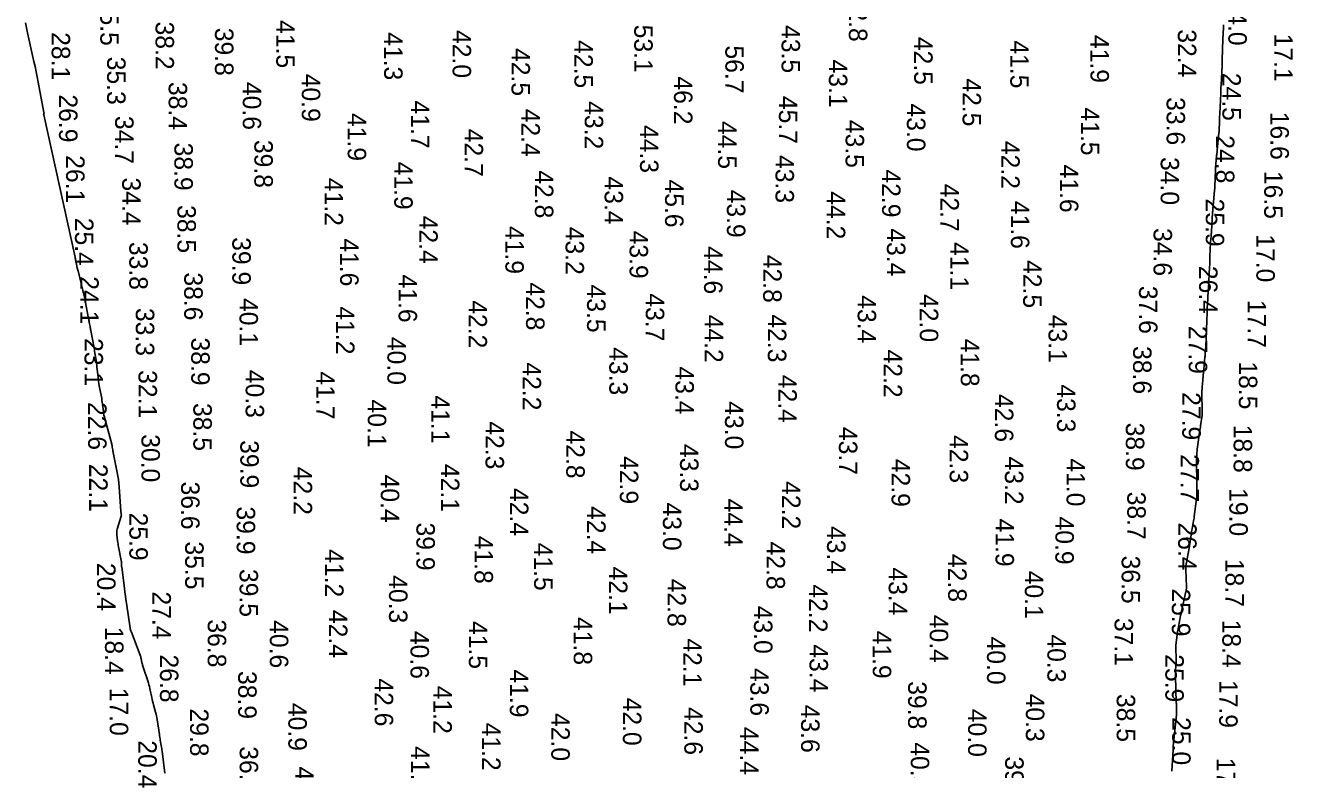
# Model space of a CAD drawing. Extents: x 1178573 to 1187098, y 693282 to 751751.
# Drawn here: x 1180803 to 1181661, y 700285 to 700789 of the extents above; entities that cross this region are included whole.
import ezdxf

# ---------------------------------------------------------------- set-up
doc = ezdxf.new("R2010")
doc.units = 0
doc.layers.add('V-HYDS-MAJR', color=7, linetype='Continuous')
doc.layers.add('V-HYDS-SOUN', color=7, linetype='Continuous')

msp = doc.modelspace()

# ---------------------------------------------------------------- linework, layer by layer
at = {"layer": 'V-HYDS-MAJR'}
for points in [[(1180897.25, 700282.8), (1180895.47, 700297.61), (1180895.35, 700298.55), (1180895.22, 700299.49), (1180895.07, 700300.43), (1180894.92, 700301.37), (1180894.28, 700305.11), (1180894.12, 700306.05), (1180893.97, 700306.98), (1180893.83, 700307.92), (1180893.69, 700308.86), (1180892.21, 700319.05), (1180892, 700320.31), (1180891.75, 700321.56), (1180891.46, 700322.8), (1180891.12, 700324.03), (1180889.69, 700328.93), (1180889.35, 700330.16), (1180889.03, 700331.4), (1180888.74, 700332.64), (1180888.47, 700333.89), (1180887.47, 700338.91), (1180887.2, 700340.16), (1180886.89, 700341.4), (1180886.55, 700342.63), (1180886.18, 700343.85), (1180882.5, 700355.26), (1180882.31, 700355.86), (1180882.14, 700356.47), (1180881.99, 700357.08), (1180881.85, 700357.7), (1180881.33, 700360.18), (1180881.19, 700360.8), (1180881.03, 700361.41), (1180880.84, 700362.01), (1180880.62, 700362.61), (1180874.68, 700378.19), (1180874.59, 700378.42), (1180874.51, 700378.65), (1180874.43, 700378.89), (1180874.36, 700379.13), (1180873.96, 700380.49), (1180873.94, 700380.56), (1180873.91, 700380.64), (1180873.87, 700380.79), (1180873.86, 700380.82), (1180873.85, 700380.86), (1180873.84, 700380.9), (1180873.84, 700380.94), (1180871.33, 700397.78), (1180870.96, 700400.3), (1180870.61, 700402.82), (1180870.27, 700405.35), (1180869.95, 700407.88), (1180868.14, 700422.31), (1180868.09, 700422.69), (1180868.06, 700423.06), (1180868.03, 700423.44), (1180868.01, 700423.82), (1180867.95, 700425.32), (1180867.93, 700425.7), (1180867.89, 700426.07), (1180867.84, 700426.45), (1180867.77, 700426.82), (1180866.03, 700435.89), (1180865.84, 700436.9), (1180865.67, 700437.91), (1180865.52, 700438.92), (1180865.38, 700439.93), (1180864.85, 700443.99), (1180864.77, 700445), (1180864.8, 700446), (1180864.93, 700446.99), (1180865.17, 700447.98), (1180867.82, 700456.82), (1180867.88, 700457.09), (1180867.91, 700457.35), (1180867.91, 700457.61), (1180867.88, 700457.88), (1180867.69, 700458.95), (1180867.65, 700459.22), (1180867.61, 700459.49), (1180867.58, 700459.76), (1180867.56, 700460.03), (1180866.37, 700476.62), (1180866.16, 700479.06), (1180865.87, 700481.48), (1180865.5, 700483.89), (1180865.06, 700486.29), (1180862.35, 700499.73), (1180862.26, 700500.2), (1180862.18, 700500.67), (1180862.1, 700501.14), (1180862.04, 700501.62), (1180861.78, 700503.52), (1180861.7, 700504), (1180861.62, 700504.47), (1180861.51, 700504.93), (1180861.4, 700505.4), (1180856.68, 700522.73), (1180856.38, 700523.95), (1180856.11, 700525.17), (1180855.89, 700526.4), (1180855.72, 700527.64), (1180855.11, 700532.61), (1180854.95, 700533.86), (1180854.77, 700535.09), (1180854.57, 700536.33), (1180854.35, 700537.56), (1180852.96, 700544.98), (1180852.7, 700546.47), (1180852.47, 700547.97), (1180852.26, 700549.47), (1180852.09, 700550.98), (1180851.39, 700557.65), (1180851.25, 700558.84), (1180851.1, 700560.02), (1180850.94, 700561.21), (1180850.76, 700562.39), (1180850, 700567.13), (1180849.81, 700568.31), (1180849.61, 700569.49), (1180849.4, 700570.67), (1180849.19, 700571.85), (1180847.22, 700582.52), (1180847.09, 700583.19), (1180846.97, 700583.87), (1180846.84, 700584.55), (1180846.72, 700585.22), (1180846.21, 700587.93), (1180846.09, 700588.6), (1180845.96, 700589.28), (1180845.83, 700589.96), (1180845.69, 700590.63), (1180842.64, 700606), (1180842.59, 700606.29), (1180842.53, 700606.57), (1180842.46, 700606.86), (1180842.4, 700607.14), (1180842.13, 700608.28), (1180842.06, 700608.56), (1180841.99, 700608.85), (1180841.92, 700609.13), (1180841.85, 700609.41), (1180838.64, 700622.76), (1180838.63, 700622.79), (1180838.62, 700622.8), (1180838.61, 700622.79), (1180838.61, 700622.76), (1180838.57, 700622.61), (1180838.57, 700622.58), (1180838.56, 700622.57), (1180838.55, 700622.58), (1180838.54, 700622.61), (1180837.99, 700624.75), (1180837.9, 700625.12), (1180837.81, 700625.49), (1180837.74, 700625.86), (1180837.66, 700626.23), (1180837.07, 700629.49), (1180836.95, 700630.16), (1180836.82, 700630.82), (1180836.68, 700631.49), (1180836.54, 700632.15), (1180815.3, 700728.32), (1180815.27, 700728.45), (1180815.27, 700728.58), (1180815.29, 700728.71), (1180815.32, 700728.84), (1180815.47, 700729.35), (1180815.5, 700729.48), (1180815.52, 700729.6), (1180815.52, 700729.73), (1180815.5, 700729.87), (1180811.56, 700750.57), (1180810.88, 700754.07), (1180810.18, 700757.55), (1180809.44, 700761.03), (1180808.69, 700764.51), (1180804.36, 700783.94), (1180803.61, 700787.36), (1180802.87, 700790.78)], [(1181614.43, 700789.25), (1181614.41, 700788.67), (1181614.34, 700786.38), (1181614.32, 700785.81), (1181614.3, 700785.24), (1181614.28, 700784.66), (1181614.25, 700784.09), (1181613.77, 700773.52), (1181613.72, 700772.27), (1181613.67, 700771.03), (1181613.63, 700769.78), (1181613.6, 700768.53), (1181613.46, 700761.77), (1181613.45, 700761.41), (1181613.44, 700761.05), (1181613.43, 700760.69), (1181613.42, 700760.33), (1181613.38, 700758.89), (1181613.36, 700758.53), (1181613.35, 700758.18), (1181613.33, 700757.82), (1181613.31, 700757.46), (1181612.77, 700748.33), (1181612.71, 700747.18), (1181612.66, 700746.04), (1181612.61, 700744.9), (1181612.57, 700743.75), (1181612.37, 700737.32), (1181612.36, 700737.1), (1181612.35, 700736.89), (1181612.34, 700736.68), (1181612.32, 700736.47), (1181612.26, 700735.62), (1181612.25, 700735.41), (1181612.23, 700735.2), (1181612.22, 700734.99), (1181612.21, 700734.78), (1181611.87, 700728.51), (1181611.81, 700727.39), (1181611.76, 700726.28), (1181611.72, 700725.16), (1181611.67, 700724.05), (1181611.45, 700717.52), (1181611.44, 700717.26), (1181611.42, 700716.99), (1181611.39, 700716.73), (1181611.36, 700716.46), (1181611.19, 700715.41), (1181611.16, 700715.15), (1181611.12, 700714.89), (1181611.09, 700714.62), (1181611.06, 700714.36), (1181609.84, 700701.59), (1181609.77, 700700.85), (1181609.7, 700700.11), (1181609.63, 700699.37), (1181609.56, 700698.63), (1181609.17, 700694.42), (1181609.16, 700694.31), (1181609.15, 700694.19), (1181609.14, 700694.07), (1181609.14, 700693.96), (1181609.1, 700693.49), (1181609.09, 700693.37), (1181609.09, 700693.25), (1181609.08, 700693.13), (1181609.07, 700693.02), (1181608.72, 700683.56), (1181608.65, 700681.95), (1181608.56, 700680.33), (1181608.44, 700678.72), (1181608.31, 700677.11), (1181607.39, 700667.07), (1181607.35, 700666.64), (1181607.32, 700666.22), (1181607.28, 700665.8), (1181607.25, 700665.37), (1181607.12, 700663.68), (1181607.09, 700663.25), (1181607.06, 700662.83), (1181607.03, 700662.41), (1181607, 700661.98), (1181606.25, 700649.5), (1181606.19, 700648.62), (1181606.13, 700647.75), (1181606.06, 700646.87), (1181605.99, 700646), (1181605.7, 700642.5), (1181605.63, 700641.63), (1181605.57, 700640.75), (1181605.53, 700639.87), (1181605.49, 700639), (1181605.23, 700630.84), (1181605.18, 700629.51), (1181605.13, 700628.19), (1181605.07, 700626.86), (1181605, 700625.53), (1181604.73, 700620.22), (1181604.66, 700618.9), (1181604.59, 700617.57), (1181604.51, 700616.24), (1181604.43, 700614.92), (1181604.05, 700608.58), (1181603.98, 700607.48), (1181603.91, 700606.38), (1181603.84, 700605.29), (1181603.77, 700604.19), (1181603.47, 700599.81), (1181603.41, 700598.71), (1181603.35, 700597.61), (1181603.3, 700596.51), (1181603.27, 700595.42), (1181603.08, 700588.38), (1181603.04, 700586.84), (1181602.99, 700585.3), (1181602.93, 700583.77), (1181602.87, 700582.23), (1181602.43, 700571.71), (1181602.4, 700571.11), (1181602.37, 700570.5), (1181602.33, 700569.89), (1181602.28, 700569.28), (1181602.09, 700566.85), (1181602.03, 700566.24), (1181601.98, 700565.63), (1181601.92, 700565.02), (1181601.86, 700564.42), (1181600.76, 700553.46), (1181600.65, 700552.3), (1181600.54, 700551.14), (1181600.43, 700549.98), (1181600.34, 700548.82), (1181599.96, 700544.17), (1181599.88, 700543.01), (1181599.83, 700541.84), (1181599.81, 700540.68), (1181599.82, 700539.51), (1181600.06, 700528.19), (1181600.06, 700527.07), (1181600.01, 700525.96), (1181599.92, 700524.84), (1181599.78, 700523.73), (1181599.12, 700519.29), (1181598.95, 700518.18), (1181598.79, 700517.07), (1181598.63, 700515.96), (1181598.47, 700514.85), (1181596.65, 700502.15), (1181596.56, 700501.4), (1181596.48, 700500.65), (1181596.42, 700499.9), (1181596.38, 700499.15), (1181596.26, 700496.14), (1181596.24, 700495.39), (1181596.22, 700494.63), (1181596.22, 700493.88), (1181596.22, 700493.12), (1181596.44, 700478.96), (1181596.45, 700478.08), (1181596.46, 700477.2), (1181596.46, 700476.32), (1181596.45, 700475.44), (1181596.43, 700471.91), (1181596.41, 700471.03), (1181596.36, 700470.16), (1181596.29, 700469.28), (1181596.18, 700468.41), (1181594.62, 700456.44), (1181594.48, 700455.4), (1181594.32, 700454.38), (1181594.15, 700453.35), (1181593.97, 700452.33), (1181593.21, 700448.23), (1181593.02, 700447.21), (1181592.84, 700446.18), (1181592.67, 700445.16), (1181592.51, 700444.13), (1181591.14, 700435.11), (1181590.94, 700433.89), (1181590.73, 700432.68), (1181590.51, 700431.48), (1181590.26, 700430.27), (1181589.26, 700425.46), (1181589.05, 700424.25), (1181588.91, 700423.04), (1181588.85, 700421.82), (1181588.87, 700420.6), (1181589.36, 700408.99), (1181589.37, 700408.72), (1181589.36, 700408.44), (1181589.34, 700408.17), (1181589.31, 700407.9), (1181589.16, 700406.83), (1181589.11, 700406.56), (1181589.07, 700406.29), (1181589.02, 700406.02), (1181588.96, 700405.75), (1181585.96, 700392.28), (1181585.66, 700390.92), (1181585.38, 700389.54), (1181585.11, 700388.17), (1181584.85, 700386.79), (1181583.71, 700380.47), (1181583.54, 700379.5), (1181583.37, 700378.53), (1181583.22, 700377.55), (1181583.07, 700376.57), (1181582.5, 700372.66), (1181582.38, 700371.68), (1181582.29, 700370.7), (1181582.24, 700369.72), (1181582.23, 700368.73), (1181582.3, 700358.75), (1181582.3, 700357.89), (1181582.28, 700357.02), (1181582.25, 700356.16), (1181582.21, 700355.3), (1181582, 700351.84), (1181581.95, 700350.98), (1181581.93, 700350.11), (1181581.92, 700349.25), (1181581.94, 700348.39), (1181582.47, 700330.69), (1181582.49, 700329.99), (1181582.51, 700329.28), (1181582.53, 700328.57), (1181582.55, 700327.87), (1181582.61, 700325.04), (1181582.62, 700324.34), (1181582.6, 700323.63), (1181582.56, 700322.93), (1181582.5, 700322.23), (1181580.73, 700305.42), (1181580.67, 700304.87), (1181580.62, 700304.31), (1181580.58, 700303.76), (1181580.54, 700303.2), (1181580.39, 700300.98), (1181580.35, 700300.43), (1181580.31, 700299.87), (1181580.28, 700299.32), (1181580.25, 700298.76), (1181579.35, 700284.18)]]:
    msp.add_lwpolyline(points, dxfattribs=at)

# ---------------------------------------------------------------- texts
at = {"layer": 'V-HYDS-SOUN'}
for s, p in [('35.5 ', (1180853.65, 700807.64)), ('42.8 ', (1181360.67, 700810.42)), ('24.0 ', (1181617.71, 700807.8)), ('38.2 ', (1180891.06, 700791.55)), ('39.8 ', (1180931.34, 700787.35)), ('41.5 ', (1180972.84, 700792.52)), ('53.1 ', (1181215.3, 700789.45)), ('43.5 ', (1181315.1, 700789.14)), ('28.1 ', (1180820.71, 700784.39)), ('41.3 ', (1181045.89, 700784.34)), ('42.0 ', (1181092.28, 700785.82)), ('42.5 ', (1181174.78, 700778.97)), ('42.5 ', (1181404.89, 700781.2)), ('41.5 ', (1181470.02, 700778.81)), ('41.9 ', (1181524.32, 700782.5)), ('32.4 ', (1181583.49, 700786.32)), ('17.1 ', (1181648.76, 700783.41)), ('42.5 ', (1181132.16, 700773.62)), ('56.7 ', (1181277, 700775.38)), ('35.3 ', (1180858.26, 700767.74)), ('43.1 ', (1181347.12, 700765.86)), ('40.9 ', (1180990.13, 700756.22)), ('46.2 ', (1181242.21, 700754.41)), ('42.5 ', (1181437.7, 700753.08)), ('24.5 ', (1181613.69, 700756.86)), ('38.4 ', (1180899.96, 700750.69)), ('40.6 ', (1180950.13, 700750.68)), ('26.9 ', (1180825.69, 700742.24)), ('41.7 ', (1181064.07, 700738.11)), ('43.2 ', (1181181.78, 700737.65)), ('45.7 ', (1181313.28, 700741.23)), ('43.0 ', (1181399.99, 700736.09)), ('33.6 ', (1181575.88, 700740.37)), ('34.7 ', (1180863.68, 700727.68)), ('41.9 ', (1181021.23, 700729.65)), ('42.4 ', (1181138.91, 700732.58)), ('41.5 ', (1181517.85, 700733.37)), ('16.6 ', (1181646.22, 700730.47)), ('42.7 ', (1181100.42, 700718.98)), ('44.3 ', (1181219.22, 700721.54)), ('44.5 ', (1181272.08, 700724.24)), ('43.5 ', (1181358.47, 700725.03)), ('38.9 ', (1180903.84, 700709.6)), ('39.8 ', (1180958.01, 700711.44)), ('42.2 ', (1181463.86, 700710.78)), ('24.8 ', (1181609.29, 700714.55)), ('26.1 ', (1180830.49, 700701.09)), ('43.3 ', (1181310.99, 700701.2)), ('41.9 ', (1181052.73, 700696.74)), ('41.6 ', (1181503.6, 700694.74)), ('34.0 ', (1181571.88, 700699.83)), ('34.4 ', (1180868.47, 700685.99)), ('41.2 ', (1181005.63, 700685.78)), ('42.8 ', (1181148, 700690.87)), ('43.4 ', (1181195.24, 700686.68)), ('45.6 ', (1181236.18, 700684.63)), ('42.9 ', (1181383.17, 700691.46)), ('16.5 ', (1181642, 700690.48)), ('43.9 ', (1181278.06, 700677.78)), ('44.2 ', (1181345.72, 700676.66)), ('42.7 ', (1181422.73, 700681.81)), ('38.5 ', (1180905.88, 700667.32)), ('41.6 ', (1181470.4, 700670.2)), ('25.9 ', (1181602.4, 700671.74)), ('25.4 ', (1180836.51, 700658.72)), ('42.4 ', (1181069.68, 700660.17)), ('41.9 ', (1181128.02, 700653.17)), ('43.2 ', (1181168.78, 700652.67)), ('43.9 ', (1181212.14, 700650.02)), ('43.4 ', (1181386.44, 700651.6)), ('34.6 ', (1181567.05, 700651.76)), ('33.8 ', (1180873.3, 700642.41)), ('39.9 ', (1180943.08, 700645.59)), ('41.6 ', (1181016.1, 700644.8)), ('41.1 ', (1181429.37, 700642.27)), ('17.0 ', (1181636.67, 700647.57)), ('44.6 ', (1181262.59, 700639.52)), ('42.8 ', (1181302.66, 700633.68)), ('42.5 ', (1181478.74, 700630.08)), ('26.4 ', (1181597.89, 700626.21)), ('24.1 ', (1180840.07, 700619.14)), ('38.6 ', (1180910.49, 700621.74)), ('41.6 ', (1181055.7, 700620.29)), ('42.8 ', (1181142.03, 700615.01)), ('43.5 ', (1181183.34, 700613.52)), ('43.7 ', (1181223.12, 700607.57)), ('43.4 ', (1181366.63, 700606.3)), ('42.0 ', (1181408.72, 700607.08)), ('37.6 ', (1181557.21, 700612.65)), ('40.1 ', (1180947.94, 700604.38)), ('41.2 ', (1181013.31, 700598.74)), ('42.2 ', (1181103.07, 700602.87)), ('17.7 ', (1181630.8, 700603.14)), ('33.3 ', (1180877.69, 700597.69)), ('44.2 ', (1181263.04, 700593.16)), ('42.3 ', (1181305.8, 700593.33)), ('43.1 ', (1181495.91, 700593.06)), ('27.9 ', (1181590.88, 700585.58)), ('23.1 ', (1180842.95, 700577.31)), ('38.9 ', (1180915.23, 700577.68)), ('40.0 ', (1181048.09, 700578.11)), ('41.8 ', (1181436.49, 700576.92)), ('43.3 ', (1181198.42, 700571.12)), ('42.2 ', (1181384.3, 700569.51)), ('38.6 ', (1181553.18, 700571.87)), ('32.1 ', (1180879.54, 700555.59)), ('40.3 ', (1180952.09, 700555.79)), ('41.7 ', (1180999.96, 700554.71)), ('42.2 ', (1181139.72, 700560.84)), ('43.4 ', (1181243.2, 700558.07)), ('18.5 ', (1181624.81, 700561.52)), ('42.4 ', (1181312.92, 700552.42)), ('41.1 ', (1181077.83, 700538.46)), ('42.6 ', (1181459.57, 700539.46)), ('43.3 ', (1181501.67, 700545.98)), ('27.9 ', (1181586.49, 700540.7)), ('22.6 ', (1180845.4, 700534.04)), ('38.5 ', (1180916.67, 700533.33)), ('40.1 ', (1181034.82, 700535.71)), ('43.0 ', (1181276.77, 700534.51)), ('42.3 ', (1181114.59, 700520.95)), ('30.0 ', (1180881.52, 700512.2)), ('42.8 ', (1181169.23, 700514.72)), ('43.7 ', (1181353.9, 700517.18)), ('38.9 ', (1181548.27, 700520.03)), ('18.8 ', (1181621.3, 700518.65)), ('39.9 ', (1180948.5, 700508.19)), ('43.3 ', (1181246.32, 700505.63)), ('42.3 ', (1181428.96, 700511.63)), ('42.9 ', (1181205.55, 700497.4)), ('42.9 ', (1181389.6, 700495.56)), ('43.2 ', (1181466.32, 700497.1)), ('41.0 ', (1181508.1, 700495.86)), ('27.7 ', (1181585.3, 700498.71)), ('22.1 ', (1180846.1, 700492.17)), ('42.2 ', (1180984.6, 700490.14)), ('42.1 ', (1181084.32, 700492.11)), ('36.6 ', (1180908.39, 700480.17)), ('40.4 ', (1181043.63, 700484.87)), ('42.2 ', (1181315.4, 700480.43)), ('42.4 ', (1181131.1, 700475.82)), ('38.7 ', (1181549.24, 700473.31)), ('19.0 ', (1181618.37, 700475.72)), ('39.9 ', (1180946.04, 700463.31)), ('42.4 ', (1181183.39, 700463.51)), ('43.0 ', (1181234.74, 700465.94)), ('44.4 ', (1181276.21, 700468.66)), ('25.9 ', (1180873.33, 700459.14)), ('39.9 ', (1181067.75, 700452.42)), ('41.9 ', (1181460.01, 700455.1)), ('40.9 ', (1181500.56, 700456.48)), ('26.4 ', (1181583.72, 700452.46)), ('41.8 ', (1181107.12, 700443.49)), ('43.4 ', (1181345.89, 700450.1)), ('35.5 ', (1180911.13, 700439.63)), ('41.5 ', (1181147.48, 700438.81)), ('42.8 ', (1181304.89, 700439.52)), ('41.2 ', (1181005.92, 700434.37)), ('42.8 ', (1181427.92, 700431.16)), ('36.5 ', (1181545.44, 700430.05)), ('18.7 ', (1181615.71, 700427.84)), ('20.4 ', (1180851.47, 700425.1)), ('39.5 ', (1180948, 700421)), ('42.1 ', (1181198.2, 700422.62)), ('43.4 ', (1181387.66, 700422.04)), ('40.1 ', (1181479.86, 700419.8)), ('40.3 ', (1181049.21, 700416.79)), ('42.8 ', (1181237.87, 700414.39)), ('42.2 ', (1181333.71, 700410.52)), ('27.4 ', (1180888.97, 700405.77)), ('25.9 ', (1181579.43, 700407.83)), ('42.4 ', (1181008.49, 700393.27)), ('43.0 ', (1181296.39, 700396.09)), ('36.8 ', (1180926.42, 700386.86)), ('40.6 ', (1180968.47, 700386.34)), ('41.5 ', (1181103.29, 700385.79)), ('41.8 ', (1181174.32, 700388.47)), ('40.4 ', (1181415.45, 700389.96)), ('37.1 ', (1181540.66, 700387.84)), ('18.4 ', (1181613.64, 700386.68)), ('18.4 ', (1180856.85, 700381.92)), ('40.6 ', (1181063.74, 700379.06)), ('41.9 ', (1181376.87, 700379.25)), ('40.0 ', (1181454.23, 700375.23)), ('40.3 ', (1181495.14, 700376.69)), ('42.1 ', (1181248.56, 700374.03)), ('43.4 ', (1181334.02, 700369.98)), ('26.8 ', (1180894.07, 700363.11)), ('25.9 ', (1181575.04, 700363.27)), ('38.9 ', (1180947.02, 700351.92)), ('41.9 ', (1181131.04, 700352.97)), ('43.6 ', (1181293.93, 700353.92)), ('42.6 ', (1181039.53, 700346.94)), ('41.2 ', (1181079.25, 700341.95)), ('39.8 ', (1181400.82, 700345)), ('17.9 ', (1181611.49, 700345.85)), ('17.0 ', (1180860.07, 700340.58)), ('42.0 ', (1181207.64, 700333.89)), ('40.3 ', (1181480.57, 700336.6)), ('38.5 ', (1181542.1, 700336.38)), ('29.8 ', (1180914.47, 700326.56)), ('40.9 ', (1180981.01, 700330.33)), ('42.0 ', (1181159.12, 700323.46)), ('42.6 ', (1181249.24, 700327.55)), ('43.6 ', (1181328.31, 700329.09)), ('40.0 ', (1181441.43, 700326.31)), ('41.2 ', (1181112.26, 700316.98)), ('25.0 ', (1181579.65, 700320.7)), ('44.4 ', (1181287, 700314.1)), ('20.4 ', (1180879.36, 700305.02)), ('36.8 ', (1180948.07, 700301)), ('41.1 ', (1181064.15, 700301.06)), ('40.5 ', (1181402.6, 700303.67)), ('39.9 ', (1181466.54, 700294.11)), ('17.6 ', (1181609.84, 700293.2)), ('41.1 ', (1180985.7, 700287.22))]:
    msp.add_text(s, height=12.5, rotation=270, dxfattribs=at).set_placement(p)

doc.saveas('drawing.dxf')
